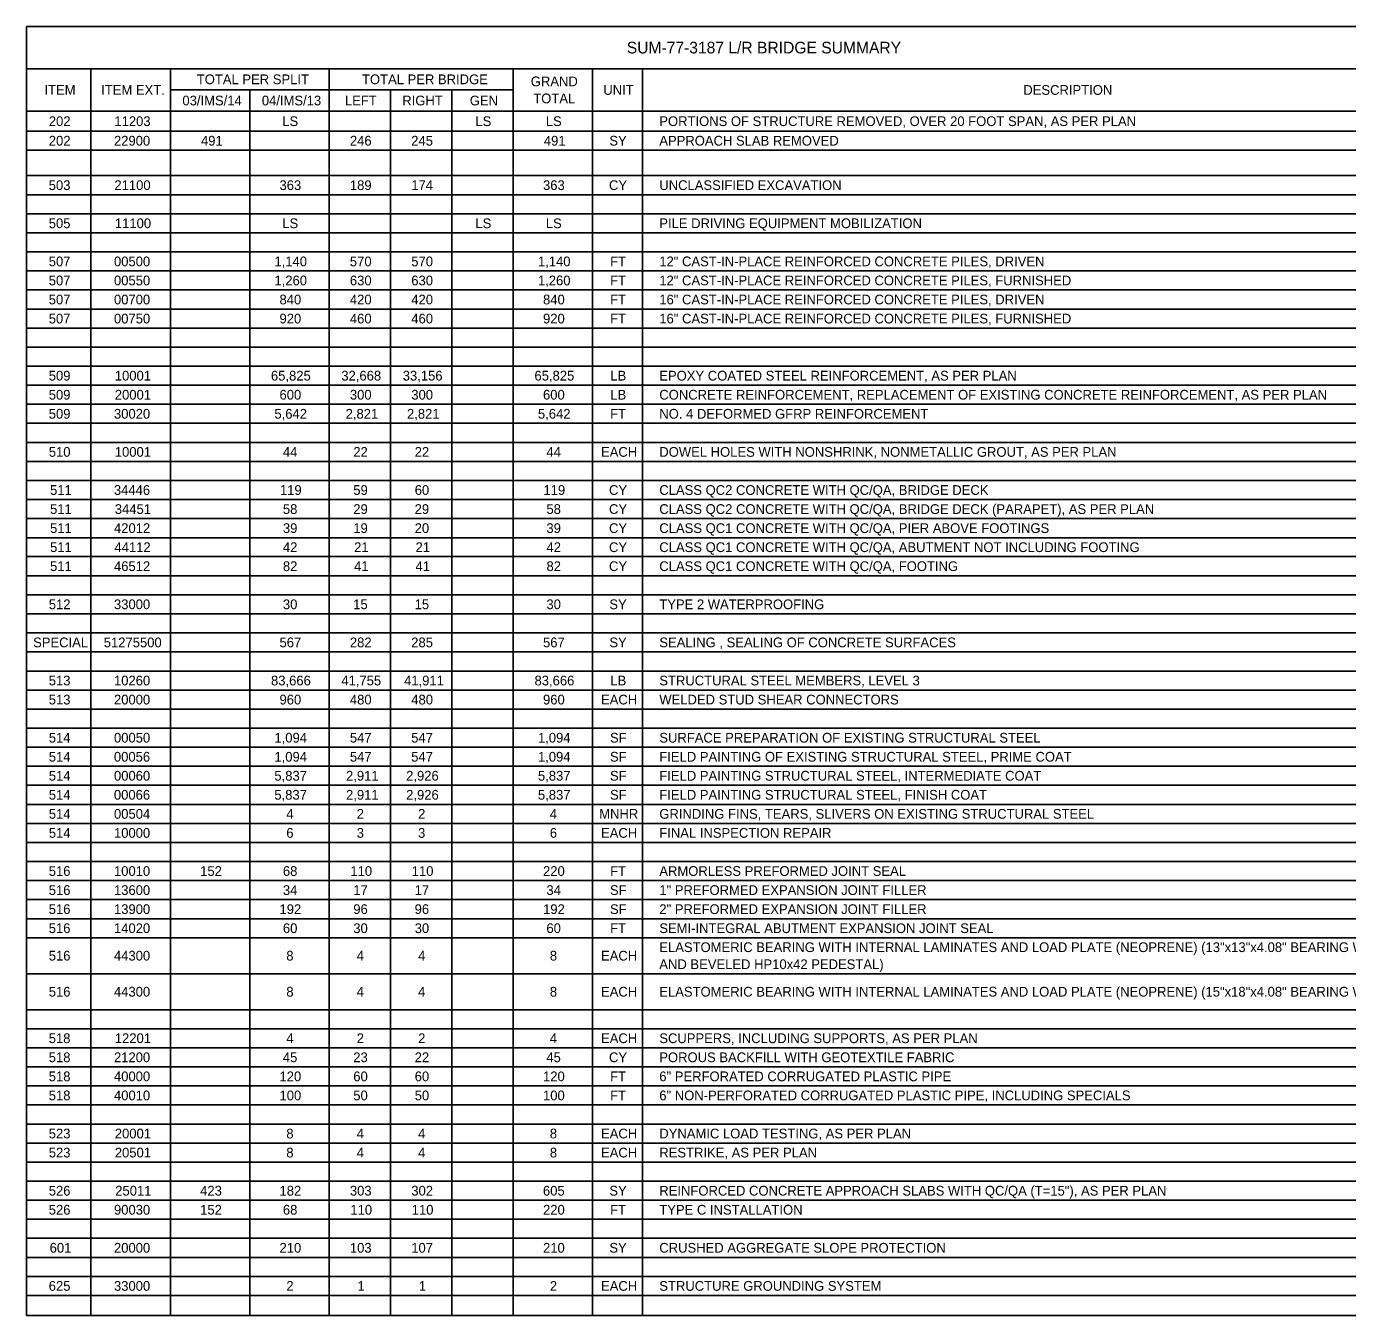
# Model space of a CAD drawing. Extents: x -62.6 to 33.3, y -2.9 to 24.9.
# Drawn here: x 2.25 to 21.24, y 1.93 to 20.46 of the extents above; entities that cross this region are included whole.
import ezdxf

# ---------------------------------------------------------------- set-up
doc = ezdxf.new("R2010")
doc.units = 0
doc.layers.add('Default', color=7, linetype='Continuous')
doc.layers.add('SH_Major_Grid_Line', color=7, linetype='Continuous')

msp = doc.modelspace()

# ---------------------------------------------------------------- linework, layer by layer
at = {"layer": 'Default'}
for p, q in [((2.248, 20.46), (31.009, 20.46)), ((2.248, 20.46), (2.248, 1.926)), ((2.248, 19.852), (31.009, 19.852)), ((3.176, 19.852), (3.176, 1.926)), ((4.318, 19.852), (4.318, 1.926)), ((6.6, 19.852), (6.6, 1.926)), ((9.248, 19.852), (9.248, 1.926)), ((10.389, 19.852), (10.389, 1.926)), ((11.105, 19.852), (11.105, 1.926)), ((4.318, 19.547), (9.248, 19.547)), ((5.459, 19.547), (5.459, 1.926)), ((7.483, 19.547), (7.483, 1.926)), ((8.365, 19.547), (8.365, 1.926)), ((2.248, 19.243), (31.009, 19.243)), ((2.248, 18.954), (31.009, 18.954)), ((2.248, 18.68), (31.009, 18.68)), ((2.248, 18.315), (31.009, 18.315)), ((2.248, 18.041), (31.009, 18.041)), ((2.248, 17.767), (31.009, 17.767)), ((2.248, 17.493), (31.009, 17.493)), ((2.248, 17.219), (31.009, 17.219)), ((2.248, 16.945), (31.009, 16.945)), ((2.248, 16.671), (31.009, 16.671)), ((2.248, 16.397), (31.009, 16.397)), ((2.248, 16.123), (31.009, 16.123)), ((2.248, 15.85), (31.009, 15.85)), ((2.248, 15.576), (31.009, 15.576)), ((2.248, 15.302), (31.009, 15.302)), ((2.248, 15.028), (31.009, 15.028)), ((2.248, 14.754), (31.009, 14.754)), ((2.248, 14.48), (31.009, 14.48)), ((2.248, 14.206), (31.009, 14.206)), ((2.248, 13.932), (31.009, 13.932)), ((2.248, 13.658), (31.009, 13.658)), ((2.248, 13.384), (31.009, 13.384)), ((2.248, 13.11), (31.009, 13.11)), ((2.248, 12.837), (31.009, 12.837)), ((2.248, 12.563), (31.009, 12.563)), ((2.248, 12.289), (31.009, 12.289)), ((2.248, 12.015), (31.009, 12.015)), ((2.248, 11.741), (31.009, 11.741)), ((2.248, 11.467), (31.009, 11.467)), ((2.248, 11.193), (31.009, 11.193)), ((2.248, 10.919), (31.009, 10.919)), ((2.248, 10.645), (31.009, 10.645)), ((2.248, 10.371), (31.009, 10.371)), ((2.248, 10.097), (31.009, 10.097)), ((2.248, 9.823), (31.009, 9.823)), ((2.248, 9.55), (31.009, 9.55)), ((2.248, 9.276), (31.009, 9.276)), ((2.248, 9.002), (31.009, 9.002)), ((2.248, 8.728), (31.009, 8.728)), ((2.248, 8.454), (31.009, 8.454)), ((2.248, 8.18), (31.009, 8.18)), ((2.248, 7.906), (31.009, 7.906)), ((2.248, 7.632), (31.009, 7.632)), ((2.248, 7.358), (31.009, 7.358)), ((2.248, 6.841), (31.009, 6.841)), ((2.248, 6.323), (31.009, 6.323)), ((2.248, 6.05), (31.009, 6.05)), ((2.248, 5.776), (31.009, 5.776)), ((2.248, 5.502), (31.009, 5.502)), ((2.248, 5.228), (31.009, 5.228)), ((2.248, 4.954), (31.009, 4.954)), ((2.248, 4.68), (31.009, 4.68)), ((2.248, 4.406), (31.009, 4.406)), ((2.248, 4.132), (31.009, 4.132)), ((2.248, 3.858), (31.009, 3.858)), ((2.248, 3.584), (31.009, 3.584)), ((2.248, 3.31), (31.009, 3.31)), ((2.248, 3.037), (31.009, 3.037)), ((2.248, 2.763), (31.009, 2.763)), ((2.248, 2.489), (31.009, 2.489)), ((2.248, 2.215), (31.009, 2.215)), ((2.248, 1.926), (31.009, 1.926))]:
    msp.add_line(p, q, dxfattribs=at)

# ---------------------------------------------------------------- texts
at = {"layer": 'SH_Major_Grid_Line'}
for s, height, p in [('SUM-77-3187 L/R BRIDGE SUMMARY', 0.168, (10.88, 20.072)), ('TOTAL PER SPLIT', 0.14, (4.698, 19.63)), ('TOTAL PER BRIDGE', 0.14, (7.073, 19.63)), ('ITEM', 0.14, (2.508, 19.477)), ('ITEM EXT.', 0.14, (3.323, 19.477)), ('GRAND ', 0.14, (9.5, 19.6)), ('UNIT', 0.14, (10.543, 19.477)), ('DESCRIPTION', 0.14, (16.582, 19.477)), ('03/IMS/14', 0.14, (4.491, 19.325)), ('04/IMS/13', 0.14, (5.633, 19.325)), ('LEFT', 0.14, (6.828, 19.325)), ('RIGHT', 0.14, (7.652, 19.325)), ('GEN', 0.14, (8.623, 19.325)), ('TOTAL', 0.14, (9.536, 19.355)), ('202', 0.14, (2.57, 19.028)), ('11203', 0.14, (3.513, 19.028)), ('LS', 0.14, (5.927, 19.028)), ('LS', 0.14, (8.704, 19.028)), ('LS', 0.14, (9.716, 19.028)), ('PORTIONS OF STRUCTURE REMOVED, OVER 20 FOOT SPAN, AS PER PLAN', 0.14, (11.348, 19.028)), ('202', 0.14, (2.57, 18.747)), ('22900', 0.14, (3.507, 18.747)), ('491', 0.14, (4.758, 18.747)), ('246', 0.14, (6.899, 18.747)), ('245', 0.14, (7.781, 18.747)), ('491', 0.14, (9.688, 18.747)), ('SY', 0.14, (10.63, 18.747)), ('APPROACH SLAB REMOVED', 0.14, (11.348, 18.747)), ('503', 0.14, (2.569, 18.108)), ('21100', 0.14, (3.513, 18.108)), ('363', 0.14, (5.887, 18.108)), ('189', 0.14, (6.899, 18.108)), ('174', 0.14, (7.782, 18.108)), ('363', 0.14, (9.676, 18.108)), ('CY', 0.14, (10.625, 18.108)), ('UNCLASSIFIED EXCAVATION', 0.14, (11.348, 18.108)), ('505', 0.14, (2.569, 17.56)), ('11100', 0.14, (3.52, 17.56)), ('LS', 0.14, (5.927, 17.56)), ('LS', 0.14, (8.704, 17.56)), ('LS', 0.14, (9.716, 17.56)), ('PILE DRIVING EQUIPMENT MOBILIZATION', 0.14, (11.348, 17.56)), ('507', 0.14, (2.569, 17.012)), ('00500', 0.14, (3.507, 17.012)), ('1,140', 0.14, (5.814, 17.012)), ('570', 0.14, (6.899, 17.012)), ('570', 0.14, (7.782, 17.012)), ('1,140', 0.14, (9.603, 17.012)), ('FT', 0.14, (10.641, 17.012)), ('12" CAST-IN-PLACE REINFORCED CONCRETE PILES, DRIVEN', 0.14, (11.348, 17.012)), ('507', 0.14, (2.569, 16.738)), ('00550', 0.14, (3.507, 16.738)), ('1,260', 0.14, (5.814, 16.738)), ('630', 0.14, (6.899, 16.738)), ('630', 0.14, (7.782, 16.738)), ('1,260', 0.14, (9.603, 16.738)), ('FT', 0.14, (10.641, 16.738)), ('12" CAST-IN-PLACE REINFORCED CONCRETE PILES, FURNISHED', 0.14, (11.348, 16.738)), ('507', 0.14, (2.569, 16.464)), ('00700', 0.14, (3.507, 16.464)), ('840', 0.14, (5.887, 16.464)), ('420', 0.14, (6.899, 16.464)), ('420', 0.14, (7.782, 16.464)), ('840', 0.14, (9.676, 16.464)), ('FT', 0.14, (10.641, 16.464)), ('16" CAST-IN-PLACE REINFORCED CONCRETE PILES, DRIVEN', 0.14, (11.348, 16.464)), ('507', 0.14, (2.569, 16.19)), ('00750', 0.14, (3.507, 16.19)), ('920', 0.14, (5.887, 16.19)), ('460', 0.14, (6.899, 16.19)), ('460', 0.14, (7.782, 16.19)), ('920', 0.14, (9.676, 16.19)), ('FT', 0.14, (10.641, 16.19)), ('16" CAST-IN-PLACE REINFORCED CONCRETE PILES, FURNISHED', 0.14, (11.348, 16.19)), ('509', 0.14, (2.569, 15.369)), ('10001', 0.14, (3.519, 15.369)), ('65,825', 0.14, (5.764, 15.369)), ('32,668', 0.14, (6.776, 15.369)), ('33,156', 0.14, (7.659, 15.369)), ('65,825', 0.14, (9.553, 15.369)), ('LB', 0.14, (10.644, 15.369)), ('EPOXY COATED STEEL REINFORCEMENT, AS PER PLAN', 0.14, (11.348, 15.369)), ('509', 0.14, (2.569, 15.095)), ('20001', 0.14, (3.519, 15.095)), ('600', 0.14, (5.887, 15.095)), ('300', 0.14, (6.899, 15.095)), ('300', 0.14, (7.782, 15.095)), ('600', 0.14, (9.676, 15.095)), ('LB', 0.14, (10.644, 15.095)), ('CONCRETE REINFORCEMENT, REPLACEMENT OF EXISTING CONCRETE REINFORCEMENT, AS PER PLAN', 0.14, (11.348, 15.095)), ('509', 0.14, (2.569, 14.821)), ('30020', 0.14, (3.507, 14.821)), ('5,642', 0.14, (5.814, 14.821)), ('2,821', 0.14, (6.838, 14.821)), ('2,821', 0.14, (7.72, 14.821)), ('5,642', 0.14, (9.603, 14.821)), ('FT', 0.14, (10.641, 14.821)), ('NO. 4 DEFORMED GFRP REINFORCEMENT', 0.14, (11.348, 14.821)), ('510', 0.14, (2.57, 14.273)), ('10001', 0.14, (3.519, 14.273)), ('44', 0.14, (5.936, 14.273)), ('22', 0.14, (6.948, 14.273)), ('22', 0.14, (7.831, 14.273)), ('44', 0.14, (9.725, 14.273)), ('EACH', 0.14, (10.51, 14.273)), ('DOWEL HOLES WITH NONSHRINK, NONMETALLIC GROUT, AS PER PLAN', 0.14, (11.348, 14.273)), ('34446', 0.14, (3.506, 13.725)), ('119', 0.14, (5.893, 13.725)), ('59', 0.14, (6.948, 13.725)), ('60', 0.14, (7.831, 13.725)), ('119', 0.14, (9.682, 13.725)), ('CY', 0.14, (10.625, 13.725)), ('CLASS QC2 CONCRETE WITH QC/QA, BRIDGE DECK', 0.14, (11.348, 13.725)), ('511', 0.14, (2.588, 13.725)), ('511', 0.14, (2.588, 13.451)), ('34451', 0.14, (3.519, 13.451)), ('58', 0.14, (5.936, 13.451)), ('29', 0.14, (6.948, 13.451)), ('29', 0.14, (7.83, 13.451)), ('58', 0.14, (9.725, 13.451)), ('CY', 0.14, (10.625, 13.451)), ('CLASS QC2 CONCRETE WITH QC/QA, BRIDGE DECK (PARAPET), AS PER PLAN', 0.14, (11.348, 13.451)), ('511', 0.14, (2.588, 13.177)), ('42012', 0.14, (3.507, 13.177)), ('39', 0.14, (5.936, 13.177)), ('19', 0.14, (6.948, 13.177)), ('20', 0.14, (7.831, 13.177)), ('39', 0.14, (9.725, 13.177)), ('CY', 0.14, (10.625, 13.177)), ('CLASS QC1 CONCRETE WITH QC/QA, PIER ABOVE FOOTINGS', 0.14, (11.348, 13.177)), ('511', 0.14, (2.588, 12.903)), ('44112', 0.14, (3.514, 12.903)), ('42', 0.14, (5.936, 12.903)), ('21', 0.14, (6.96, 12.903)), ('21', 0.14, (7.843, 12.903)), ('42', 0.14, (9.726, 12.903)), ('CY', 0.14, (10.625, 12.903)), ('CLASS QC1 CONCRETE WITH QC/QA, ABUTMENT NOT INCLUDING FOOTING', 0.14, (11.348, 12.903)), ('511', 0.14, (2.588, 12.63)), ('46512', 0.14, (3.507, 12.63)), ('82', 0.14, (5.936, 12.63)), ('41', 0.14, (6.96, 12.63)), ('41', 0.14, (7.843, 12.63)), ('82', 0.14, (9.726, 12.63)), ('CY', 0.14, (10.625, 12.63)), ('CLASS QC1 CONCRETE WITH QC/QA, FOOTING', 0.14, (11.348, 12.63)), ('512', 0.14, (2.57, 12.082)), ('33000', 0.14, (3.507, 12.082)), ('30', 0.14, (5.936, 12.082)), ('15', 0.14, (6.947, 12.082)), ('15', 0.14, (7.83, 12.082)), ('30', 0.14, (9.725, 12.082)), ('SY', 0.14, (10.63, 12.082)), ('TYPE 2 WATERPROOFING', 0.14, (11.348, 12.082)), ('SPECIAL', 0.14, (2.344, 11.534)), ('51275500', 0.14, (3.36, 11.534)), ('567', 0.14, (5.887, 11.534)), ('282', 0.14, (6.899, 11.534)), ('285', 0.14, (7.781, 11.534)), ('567', 0.14, (9.676, 11.534)), ('SY', 0.14, (10.63, 11.534)), ('SEALING , SEALING OF CONCRETE SURFACES', 0.14, (11.348, 11.534)), ('513', 0.14, (2.569, 10.986)), ('10260', 0.14, (3.507, 10.986)), ('83,666', 0.14, (5.765, 10.986)), ('41,755', 0.14, (6.776, 10.986)), ('41,911', 0.14, (7.678, 10.986)), ('83,666', 0.14, (9.554, 10.986)), ('LB', 0.14, (10.644, 10.986)), ('STRUCTURAL STEEL MEMBERS, LEVEL 3', 0.14, (11.348, 10.986)), ('513', 0.14, (2.569, 10.712)), ('20000', 0.14, (3.507, 10.712)), ('960', 0.14, (5.887, 10.712)), ('480', 0.14, (6.899, 10.712)), ('480', 0.14, (7.782, 10.712)), ('960', 0.14, (9.676, 10.712)), ('EACH', 0.14, (10.51, 10.712)), ('WELDED STUD SHEAR CONNECTORS', 0.14, (11.348, 10.712)), ('514', 0.14, (2.57, 10.164)), ('00050', 0.14, (3.507, 10.164)), ('1,094', 0.14, (5.814, 10.164)), ('547', 0.14, (6.899, 10.164)), ('547', 0.14, (7.781, 10.164)), ('1,094', 0.14, (9.603, 10.164)), ('SF', 0.14, (10.639, 10.164)), ('SURFACE PREPARATION OF EXISTING STRUCTURAL STEEL', 0.14, (11.348, 10.164)), ('514', 0.14, (2.57, 9.89)), ('00056', 0.14, (3.506, 9.89)), ('1,094', 0.14, (5.814, 9.89)), ('547', 0.14, (6.899, 9.89)), ('547', 0.14, (7.781, 9.89)), ('1,094', 0.14, (9.603, 9.89)), ('SF', 0.14, (10.639, 9.89)), ('FIELD PAINTING OF EXISTING STRUCTURAL STEEL, PRIME COAT', 0.14, (11.348, 9.89)), ('514', 0.14, (2.57, 9.617)), ('00060', 0.14, (3.507, 9.617)), ('5,837', 0.14, (5.813, 9.617)), ('2,911', 0.14, (6.844, 9.617)), ('2,926', 0.14, (7.708, 9.617)), ('5,837', 0.14, (9.603, 9.617)), ('SF', 0.14, (10.639, 9.617)), ('FIELD PAINTING STRUCTURAL STEEL, INTERMEDIATE COAT', 0.14, (11.348, 9.617)), ('514', 0.14, (2.57, 9.343)), ('00066', 0.14, (3.506, 9.343)), ('5,837', 0.14, (5.813, 9.343)), ('2,911', 0.14, (6.844, 9.343)), ('2,926', 0.14, (7.708, 9.343)), ('5,837', 0.14, (9.603, 9.343)), ('SF', 0.14, (10.639, 9.343)), ('FIELD PAINTING STRUCTURAL STEEL, FINISH COAT', 0.14, (11.348, 9.343)), ('514', 0.14, (2.57, 9.069)), ('00504', 0.14, (3.507, 9.069)), ('4', 0.14, (5.985, 9.069)), ('2', 0.14, (6.997, 9.069)), ('2', 0.14, (7.88, 9.069)), ('4', 0.14, (9.774, 9.069)), ('MNHR', 0.14, (10.484, 9.069)), ('GRINDING FINS, TEARS, SLIVERS ON EXISTING STRUCTURAL STEEL', 0.14, (11.348, 9.069)), ('514', 0.14, (2.57, 8.795)), ('10000', 0.14, (3.507, 8.795)), ('6', 0.14, (5.985, 8.795)), ('3', 0.14, (6.997, 8.795)), ('3', 0.14, (7.879, 8.795)), ('6', 0.14, (9.774, 8.795)), ('EACH', 0.14, (10.51, 8.795)), ('FINAL INSPECTION REPAIR', 0.14, (11.348, 8.795)), ('516', 0.14, (2.569, 8.247)), ('10010', 0.14, (3.507, 8.247)), ('152', 0.14, (4.746, 8.247)), ('68', 0.14, (5.936, 8.247)), ('110', 0.14, (6.906, 8.247)), ('110', 0.14, (7.788, 8.247)), ('220', 0.14, (9.676, 8.247)), ('FT', 0.14, (10.641, 8.247)), ('ARMORLESS PREFORMED JOINT SEAL', 0.14, (11.348, 8.247)), ('516', 0.14, (2.569, 7.973)), ('13600', 0.14, (3.507, 7.973)), ('34', 0.14, (5.936, 7.973)), ('17', 0.14, (6.948, 7.973)), ('17', 0.14, (7.83, 7.973)), ('34', 0.14, (9.725, 7.973)), ('SF', 0.14, (10.639, 7.973)), ('1" PREFORMED EXPANSION JOINT FILLER', 0.14, (11.348, 7.973)), ('516', 0.14, (2.569, 7.699)), ('13900', 0.14, (3.507, 7.699)), ('192', 0.14, (5.887, 7.699)), ('96', 0.14, (6.948, 7.699)), ('96', 0.14, (7.83, 7.699)), ('192', 0.14, (9.677, 7.699)), ('SF', 0.14, (10.639, 7.699)), ('2" PREFORMED EXPANSION JOINT FILLER', 0.14, (11.348, 7.699)), ('516', 0.14, (2.569, 7.425)), ('14020', 0.14, (3.507, 7.425)), ('60', 0.14, (5.936, 7.425)), ('30', 0.14, (6.948, 7.425)), ('30', 0.14, (7.831, 7.425)), ('60', 0.14, (9.725, 7.425)), ('FT', 0.14, (10.641, 7.425)), ('SEMI-INTEGRAL ABUTMENT EXPANSION JOINT SEAL', 0.14, (11.348, 7.425)), ('ELASTOMERIC BEARING WITH INTERNAL LAMINATES AND LOAD PLATE (NEOPRENE) (13"x13"x4.08" BEARING WITH 14"x14" LOAD PLATE ', 0.14, (11.348, 7.152)), ('516', 0.14, (2.569, 7.03)), ('44300', 0.14, (3.507, 7.03)), ('8', 0.14, (5.985, 7.03)), ('4', 0.14, (6.997, 7.03)), ('4', 0.14, (7.88, 7.03)), ('8', 0.14, (9.774, 7.03)), ('EACH', 0.14, (10.51, 7.03)), ('AND BEVELED HP10x42 PEDESTAL)', 0.14, (11.348, 6.907)), ('516', 0.14, (2.569, 6.512)), ('44300', 0.14, (3.507, 6.512)), ('8', 0.14, (5.985, 6.512)), ('4', 0.14, (6.997, 6.512)), ('4', 0.14, (7.88, 6.512)), ('8', 0.14, (9.774, 6.512)), ('EACH', 0.14, (10.51, 6.512)), ('ELASTOMERIC BEARING WITH INTERNAL LAMINATES AND LOAD PLATE (NEOPRENE) (15"x18"x4.08" BEARING WITH 16"x19" LOAD PLATE)', 0.14, (11.348, 6.512)), ('518', 0.14, (2.569, 5.843)), ('12201', 0.14, (3.519, 5.843)), ('4', 0.14, (5.985, 5.843)), ('2', 0.14, (6.997, 5.843)), ('2', 0.14, (7.88, 5.843)), ('4', 0.14, (9.774, 5.843)), ('EACH', 0.14, (10.51, 5.843)), ('SCUPPERS, INCLUDING SUPPORTS, AS PER PLAN', 0.14, (11.348, 5.843)), ('518', 0.14, (2.569, 5.569)), ('21200', 0.14, (3.507, 5.569)), ('45', 0.14, (5.935, 5.569)), ('23', 0.14, (6.948, 5.569)), ('22', 0.14, (7.831, 5.569)), ('45', 0.14, (9.724, 5.569)), ('CY', 0.14, (10.625, 5.569)), ('POROUS BACKFILL WITH GEOTEXTILE FABRIC', 0.14, (11.348, 5.569)), ('518', 0.14, (2.569, 5.295)), ('40000', 0.14, (3.507, 5.295)), ('120', 0.14, (5.887, 5.295)), ('60', 0.14, (6.948, 5.295)), ('60', 0.14, (7.831, 5.295)), ('120', 0.14, (9.676, 5.295)), ('FT', 0.14, (10.641, 5.295)), ('6" PERFORATED CORRUGATED PLASTIC PIPE', 0.14, (11.348, 5.295)), ('518', 0.14, (2.569, 5.021)), ('40010', 0.14, (3.507, 5.021)), ('100', 0.14, (5.887, 5.021)), ('50', 0.14, (6.948, 5.021)), ('50', 0.14, (7.831, 5.021)), ('100', 0.14, (9.676, 5.021)), ('FT', 0.14, (10.641, 5.021)), ('6" NON-PERFORATED CORRUGATED PLASTIC PIPE, INCLUDING SPECIALS', 0.14, (11.348, 5.021)), ('523', 0.14, (2.569, 4.473)), ('20001', 0.14, (3.519, 4.473)), ('8', 0.14, (5.985, 4.473)), ('4', 0.14, (6.997, 4.473)), ('4', 0.14, (7.88, 4.473)), ('8', 0.14, (9.774, 4.473)), ('EACH', 0.14, (10.51, 4.473)), ('DYNAMIC LOAD TESTING, AS PER PLAN', 0.14, (11.348, 4.473)), ('523', 0.14, (2.569, 4.199)), ('20501', 0.14, (3.519, 4.199)), ('8', 0.14, (5.985, 4.199)), ('4', 0.14, (6.997, 4.199)), ('4', 0.14, (7.88, 4.199)), ('8', 0.14, (9.774, 4.199)), ('EACH', 0.14, (10.51, 4.199)), ('RESTRIKE, AS PER PLAN', 0.14, (11.348, 4.199)), ('526', 0.14, (2.569, 3.651)), ('25011', 0.14, (3.525, 3.651)), ('423', 0.14, (4.746, 3.651)), ('182', 0.14, (5.887, 3.651)), ('303', 0.14, (6.899, 3.651)), ('302', 0.14, (7.782, 3.651)), ('605', 0.14, (9.675, 3.651)), ('SY', 0.14, (10.63, 3.651)), ('REINFORCED CONCRETE APPROACH SLABS WITH QC/QA (T=15"), AS PER PLAN', 0.14, (11.348, 3.651)), ('526', 0.14, (2.569, 3.377)), ('90030', 0.14, (3.507, 3.377)), ('152', 0.14, (4.746, 3.377)), ('68', 0.14, (5.936, 3.377)), ('110', 0.14, (6.906, 3.377)), ('110', 0.14, (7.788, 3.377)), ('220', 0.14, (9.676, 3.377)), ('FT', 0.14, (10.641, 3.377)), ('TYPE C INSTALLATION', 0.14, (11.348, 3.377)), ('601', 0.14, (2.582, 2.83)), ('20000', 0.14, (3.507, 2.83)), ('210', 0.14, (5.887, 2.83)), ('103', 0.14, (6.899, 2.83)), ('107', 0.14, (7.781, 2.83)), ('210', 0.14, (9.676, 2.83)), ('SY', 0.14, (10.63, 2.83)), ('CRUSHED AGGREGATE SLOPE PROTECTION', 0.14, (11.348, 2.83)), ('625', 0.14, (2.569, 2.282)), ('33000', 0.14, (3.507, 2.282)), ('2', 0.14, (5.985, 2.282)), ('1', 0.14, (7.009, 2.282)), ('1', 0.14, (7.891, 2.282)), ('2', 0.14, (9.774, 2.282)), ('EACH', 0.14, (10.51, 2.282)), ('STRUCTURE GROUNDING SYSTEM', 0.14, (11.348, 2.282))]:
    msp.add_text(s, height=height, dxfattribs=at).set_placement(p)

doc.saveas('drawing.dxf')
